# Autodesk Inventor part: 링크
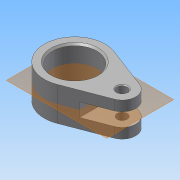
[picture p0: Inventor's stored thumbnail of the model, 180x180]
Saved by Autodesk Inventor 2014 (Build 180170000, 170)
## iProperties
Created: 2015-12
Part Number: 링크
Material: 강철, 연강
Document SubType Name: Modeling
Designer: mduedu
Density: 7.86 g/cm^3
Appearance: 강철
Author: mduedu
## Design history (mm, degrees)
sketch "스케치1"
  geometry: L1 (6.429, -16.813)-(30.857, -7.472); L2 (6.429, 16.813)-(30.857, 7.472); A1 r 18 centre (0, 0) between (6.429, 16.813) and (6.429, -16.813); A2 r 8 centre (28, 0) between (30.857, -7.472) and (30.857, 7.472); 1 further point
  constraints: 4 end point, 4 point on circle, 4 tangent, 2 centre point, 1 coincident, 1 horizontal alignment
  dimensions: "d0" = 18 radius of A1; "d1" = 8 radius of A2; "d2" = 28 distance of A2.centre point (0, 0)
extrude "돌출1" new body sketch "스케치1" stored distance "d3" = 20; taper "d4" = 0 deg
sketch "스케치2"
  geometry: L1 (6.429, 16.813)-(30.857, 7.472) reference; L2 (30.857, -7.472)-(6.429, -16.813) reference; L3 (16, 13.153)-(16, -13.153); A1 r 8 centre (28, 0) between (30.857, -7.472) and (30.857, 7.472) reference; 1 further point
  constraints: 2 end point, 2 point on line, 1 vertical
  dimensions: "d5" = 20 dimension on A1 L3
extrude "돌출2" cut sketch "스케치2" stored distance "d6" = 8; taper "d7" = 0 deg
hole "구멍1" diameter "d10" = 26; stored, may be unused: countersink angle "d14" = 90 deg, drill point angle "d16" = 118 deg; dims "d8" = 10, "d9" = 10, "d11" = 6, "d12" = 4, "d13" = 2, "d15" = 8
hole "구멍2" diameter "d19" = 6; stored, may be unused: countersink angle "d23" = 90 deg, drill point angle "d25" = 118 deg; dims "d20" = 6, "d21" = 4, "d22" = 2, "d24" = 8, "d32" = 10, "d33" = 10
chamfer "모따기1" distance "d26" = 1; stored, may be unused: second distance "d27" = 2, angle "d28" = 45 deg
chamfer "모따기2" distance "d29" = 0.5; stored, may be unused: second distance "d30" = 2, angle "d31" = 45 deg
node "작업 평면1"
node "솔리드1"
